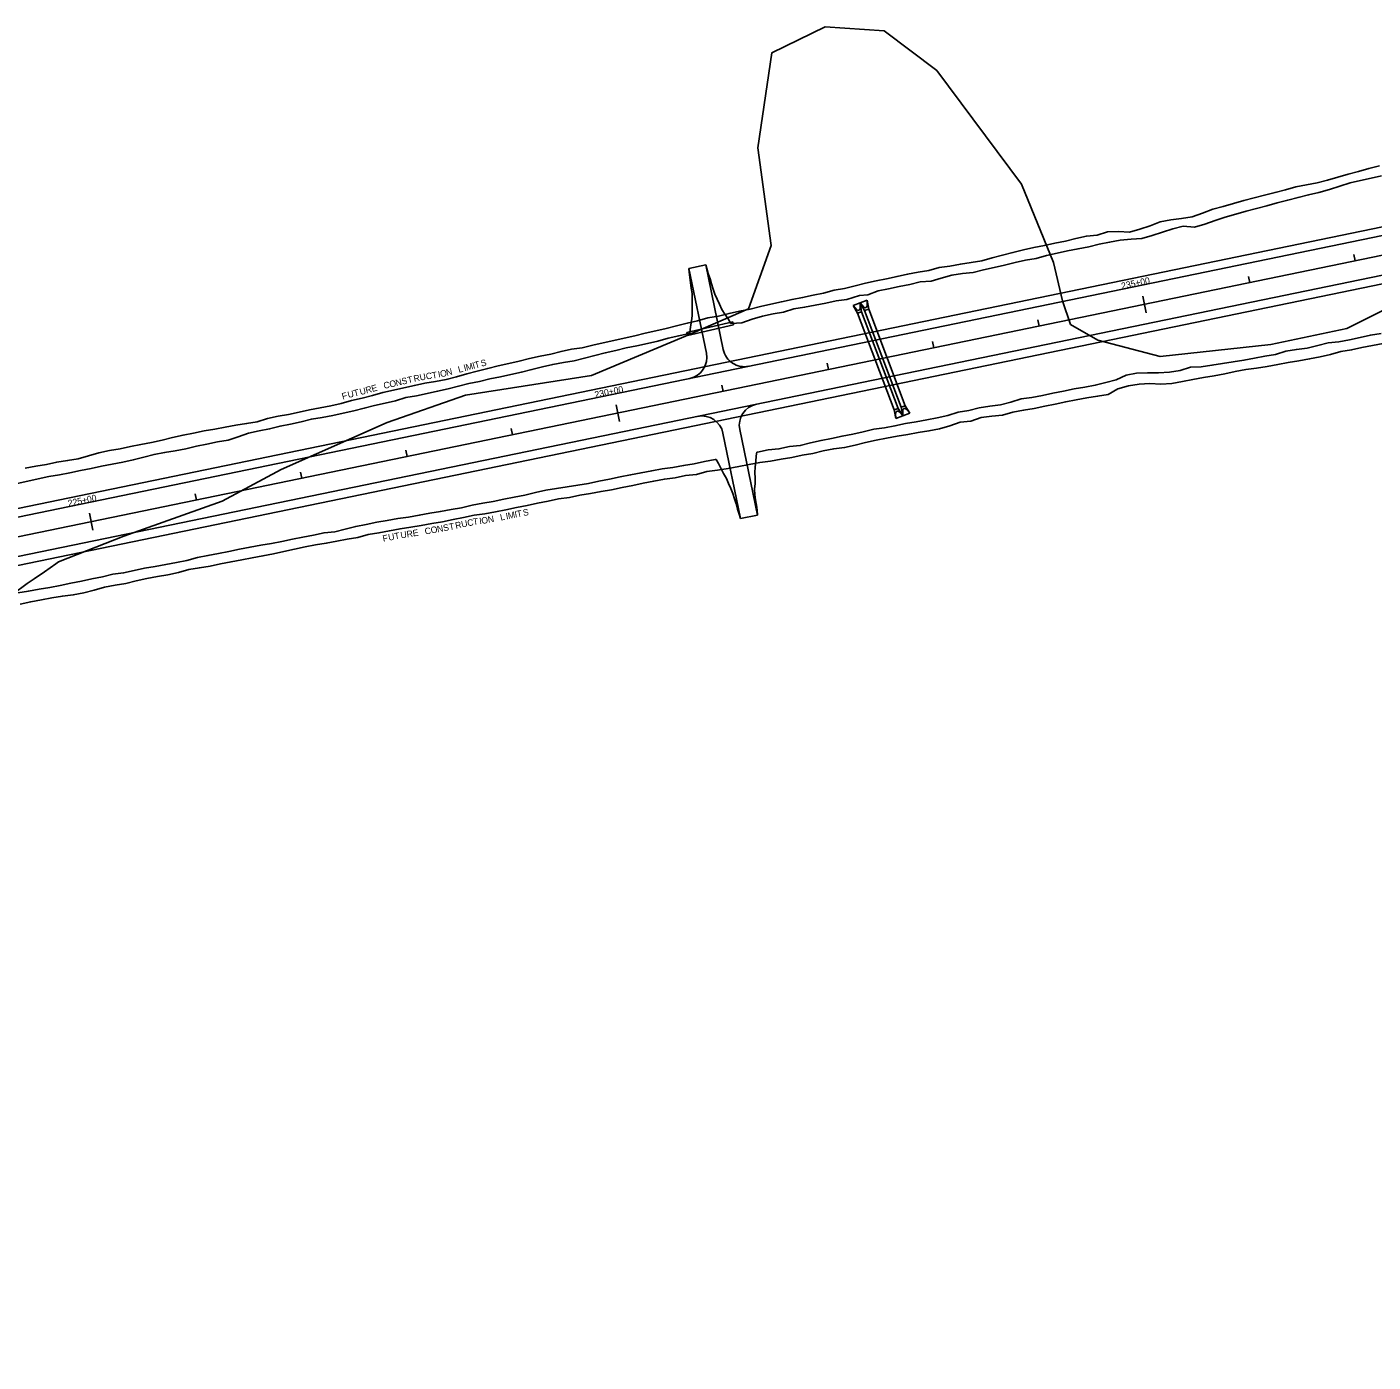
# Model space of a CAD drawing. Extents: x 979959 to 994833, y 1835619 to 1845316.
# Drawn here: x 988176 to 989427, y 1837739 to 1838981 of the extents above; entities that cross this region are included whole.
import ezdxf

# ---------------------------------------------------------------- set-up
doc = ezdxf.new("R2010")
doc.units = 0
for name, color, linetype in [('43', 7, 'Continuous'), ('Future 5 Lane Construction Limits', 7, 'Continuous'), ('R_Drainage', 7, 'Continuous'), ('R_Horz Alg', 7, 'Continuous'), ('R_Horz Alg Stationing', 7, 'Continuous'), ('R_Proposed Const Limits', 7, 'Continuous'), ('R_Proposed Road', 7, 'Continuous')]:
    doc.layers.add(name, color=color, linetype=linetype)

msp = doc.modelspace()

# ---------------------------------------------------------------- linework, layer by layer
at = {"layer": '43'}
msp.add_lwpolyline([(988162.8, 1838452.8), (988176.1, 1838462.9), (988182.4, 1838467.2), (988192, 1838473.5), (988202.5, 1838481), (988205.2, 1838483), (988266, 1838506.7), (988357.2, 1838539.5), (988412, 1838568.7), (988510.6, 1838612.5), (988583.6, 1838638.1), (988700.5, 1838656.4), (988788.1, 1838692.9), (988846.5, 1838718.4), (988867.6, 1838777.2), (988855.3, 1838867.9), (988868.4, 1838956.4), (988917.8, 1838980.5), (988972.9, 1838976.8), (989021.6, 1838940.1), (989100.5, 1838834.2), (989130.3, 1838761.3), (989138.6, 1838725.7), (989145.9, 1838703.8), (989171.4, 1838689.2), (989229.4, 1838673.9), (989332.3, 1838685.2), (989403, 1838700.1), (989504.6, 1838750.9)], dxfattribs=at)
at = {"layer": 'Future 5 Lane Construction Limits'}
for points in [[(988389.8, 1838613.2), (988399.4, 1838616.2), (988409.2, 1838618.4), (988419, 1838620.1), (988428.8, 1838622.1), (988438.6, 1838624.3), (988448.4, 1838626.3), (988458.2, 1838628), (988468, 1838630.3), (988477.6, 1838633), (988487.4, 1838635.3), (988497, 1838637.8), (988506.7, 1838640.5), (988516.5, 1838642.6), (988526.2, 1838644.9), (988536, 1838647.1), (988545.7, 1838649.2), (988555.6, 1838650.7), (988565.5, 1838652.6), (988575.2, 1838655), (988584.8, 1838657.7), (988594.5, 1838660.3), (988604.2, 1838662.9), (988613.9, 1838665.2), (988623.7, 1838667.3), (988633.4, 1838669.6), (988643.1, 1838672.1), (988652.9, 1838674.1), (988662.8, 1838676), (988672.4, 1838678.6), (988682.2, 1838680.8), (988692.1, 1838682.1), (988701.9, 1838684.4), (988711.6, 1838686.6), (988721.4, 1838688.8), (988731.1, 1838691.1), (988740.9, 1838693.2), (988750.6, 1838695.5), (988760.4, 1838697.7), (988770.1, 1838700), (988779.8, 1838702.5), (988789.6, 1838704.8), (988799.3, 1838707.1), (988808.9, 1838709.8), (988818.8, 1838711.6), (988828.5, 1838714), (988838.3, 1838716), (988848.1, 1838718.1), (988857.8, 1838720.4), (988867.5, 1838722.7), (988877.3, 1838724.9), (988887.1, 1838727), (988896.9, 1838728.8), (988906.7, 1838730.9), (988916.5, 1838732.9), (988926.2, 1838735.5), (988936, 1838737.3), (988945.7, 1838739.6), (988955.4, 1838742.2), (988965.2, 1838744.2), (988975, 1838746.2), (988984.7, 1838748.5), (988994.6, 1838750.4), (989004.4, 1838752.3), (989014.2, 1838754), (989023.9, 1838756.6), (989033.8, 1838758.1), (989043.7, 1838759.9), (989053.6, 1838761.4), (989063.5, 1838762.8), (989073.1, 1838765.7), (989082.8, 1838768.3), (989092.5, 1838770.6), (989102.2, 1838773), (989112, 1838775.2), (989121.7, 1838777.3), (989131.5, 1838779.3), (989141.3, 1838781.3), (989151.1, 1838783.7), (989160.8, 1838785.9), (989170.8, 1838786.8), (989180.4, 1838789.9), (989190.5, 1838790.3), (989200.9, 1838789.7), (989210.5, 1838792.4), (989220.1, 1838795.6), (989229.5, 1838799.3), (989239.3, 1838801.2), (989249.3, 1838802.4), (989259.2, 1838803.9), (989268.7, 1838807.4), (989278.2, 1838810.9), (989287.9, 1838813.5), (989297.5, 1838816.2), (989307.2, 1838818.9), (989316.8, 1838821.5), (989326.5, 1838824.1), (989336.2, 1838826.6), (989345.9, 1838829), (989355.6, 1838831.6), (989365.4, 1838833.6), (989375.2, 1838835.6), (989384.9, 1838838), (989394.5, 1838840.8), (989404.2, 1838843.5), (989413.9, 1838846), (989423.5, 1838848.7), (989433.2, 1838851.4)], [(988169.5, 1838443.6), (988179.3, 1838445.8), (988189.2, 1838447.5), (988199, 1838449.3), (988208.8, 1838451.1), (988218.8, 1838452.2), (988228.6, 1838454.2), (988238.3, 1838456.7), (988248, 1838459.3), (988257.8, 1838461.2), (988267.7, 1838462.8), (988277.4, 1838465.2), (988287.2, 1838467.3), (988297, 1838469.2), (988306.9, 1838470.9), (988316.6, 1838473), (988326.3, 1838475.8), (988336.1, 1838477.5), (988346, 1838479), (988355.8, 1838481.1), (988365.6, 1838483), (988375.5, 1838484.8), (988385.3, 1838486.8), (988395.1, 1838488.4), (988404.9, 1838490.5), (988414.7, 1838492.6), (988424.5, 1838494.7), (988434.3, 1838496.8), (988444.1, 1838498.7), (988454, 1838500.2), (988463.8, 1838502.1), (988473.6, 1838503.9), (988483.5, 1838505.7), (988493.1, 1838508.4), (988503, 1838509.9), (988512.8, 1838511.9), (988522.7, 1838513.7), (988532.6, 1838515.2), (988542.4, 1838516.8), (988552.3, 1838518.5), (988562.2, 1838520.2), (988572, 1838522.2), (988581.7, 1838524.3), (988591.5, 1838526.3), (988601.5, 1838527.6), (988611.3, 1838529.4), (988621.1, 1838531.4), (988630.9, 1838533.4), (988640.7, 1838535.4), (988650.5, 1838537.5), (988660.3, 1838539.5), (988670.1, 1838541.5), (988680.1, 1838542.7), (988689.8, 1838544.8), (988699.7, 1838546.6), (988709.5, 1838548.4), (988719.4, 1838550), (988729.2, 1838552.1), (988739, 1838553.9), (988748.7, 1838556.2), (988758.6, 1838558.1), (988768.4, 1838559.9), (988778.4, 1838561.2), (988788.2, 1838563.1), (988798.2, 1838564.1), (988807.8, 1838566.9), (988817.8, 1838568.1), (988827.7, 1838569.7), (988837.5, 1838571.6), (988847.3, 1838573.4), (988857.1, 1838575.2), (988867, 1838576.7), (988876.9, 1838578.4), (988886.8, 1838580), (988896.6, 1838582.1), (988906.4, 1838583.8), (988916.1, 1838586.1), (988925.9, 1838588.2), (988935.9, 1838589.2), (988945.7, 1838591.5), (988955.4, 1838594), (988965.2, 1838596), (988975, 1838598), (988984.8, 1838599.8), (988994.7, 1838601.4), (989004.5, 1838603.1), (989014.4, 1838604.7), (989024.3, 1838606.6), (989033.9, 1838609.5), (989043.4, 1838612.7), (989053.4, 1838613.7), (989062.9, 1838617.1), (989072.9, 1838618.3), (989082.9, 1838619.3), (989092.5, 1838622.3), (989102.4, 1838623.9), (989112.2, 1838625.6), (989122, 1838627.6), (989131.8, 1838629.7), (989141.6, 1838631.9), (989151.4, 1838633.7), (989161.2, 1838635.5), (989171.1, 1838637), (989181, 1838638.7), (989190.1, 1838643.9), (989199.8, 1838646.7), (989209.7, 1838648.1), (989219.8, 1838648.8), (989230.1, 1838648.1), (989240.2, 1838648.8), (989250, 1838650.7), (989259.8, 1838652.6), (989269.7, 1838654.3), (989279.5, 1838655.9), (989289.4, 1838657.8), (989299.1, 1838660), (989309, 1838661.8), (989318.9, 1838663.2), (989328.8, 1838664.6), (989338.7, 1838666.4), (989348.5, 1838668.3), (989358.3, 1838670), (989368.2, 1838671.7), (989378, 1838673.7), (989387.8, 1838675.7), (989397.4, 1838678.5), (989407.3, 1838680), (989417, 1838682.4), (989426.9, 1838684.2), (989436.7, 1838686)], [(988174.1, 1838570.2), (988183.9, 1838571.9), (988193.8, 1838573.4), (988203.5, 1838575.8), (988213.5, 1838577.1), (988223.3, 1838578.8), (988233, 1838581.4), (988242.6, 1838584.2), (988252.4, 1838586.4), (988262.3, 1838587.9), (988272.1, 1838590.1), (988281.8, 1838592.1), (988291.7, 1838594), (988301.4, 1838596.2), (988311.1, 1838598.6), (988320.9, 1838600.8), (988330.7, 1838602.7), (988340.5, 1838604.7), (988350.4, 1838606.3), (988360.2, 1838608.3), (988370, 1838610), (988380, 1838611.5), (988389.8, 1838613.2)]]:
    msp.add_lwpolyline(points, dxfattribs=at)
at = {"layer": 'R_Drainage'}
for p, q in [((988943.8, 1838721.3), (988950.4, 1838723.7)), ((988948.1, 1838714.1), (988943.8, 1838721.3)), ((988947.2, 1838717.4), (988943.8, 1838721.3)), ((988950.4, 1838723.7), (988956.9, 1838726.2)), ((988951.8, 1838715.6), (988950.4, 1838723.7)), ((988950.4, 1838718.6), (988950.4, 1838723.7)), ((988954.6, 1838716.6), (988950.4, 1838723.7)), ((988953.7, 1838719.9), (988950.4, 1838723.7)), ((988954.6, 1838716.6), (988958.4, 1838718)), ((988958.4, 1838718), (988956.9, 1838726.2)), ((988956.9, 1838721.1), (988956.9, 1838726.2)), ((988958.4, 1838718), (988992.3, 1838628.2)), ((988789.2, 1838696.4), (988832.1, 1838706.2)), ((988832.8, 1838703.3), (988832.1, 1838706.2)), ((988948.1, 1838714.1), (988951.8, 1838715.6)), ((988948.1, 1838714.1), (988982, 1838624.3)), ((988951.8, 1838715.6), (988985.7, 1838625.7)), ((988954.6, 1838716.6), (988988.5, 1838626.8)), ((988789.9, 1838693.5), (988789.2, 1838696.4)), ((988789.9, 1838693.5), (988832.8, 1838703.3)), ((988982, 1838624.3), (988985.7, 1838625.7)), ((988982, 1838624.3), (988983.5, 1838616.2)), ((988983.4, 1838621.3), (988983.5, 1838616.2)), ((988983.5, 1838616.2), (988990, 1838618.6)), ((988985.7, 1838625.7), (988990, 1838618.6)), ((988986.6, 1838622.5), (988990, 1838618.6)), ((988988.5, 1838626.8), (988992.3, 1838628.2)), ((988988.5, 1838626.8), (988990, 1838618.6)), ((988990, 1838623.7), (988990, 1838618.6)), ((988990, 1838618.6), (988996.6, 1838621.1)), ((988992.3, 1838628.2), (988996.6, 1838621.1)), ((988993.2, 1838625), (988996.6, 1838621.1))]:
    msp.add_line(p, q, dxfattribs=at)
for centre, start, end in [((988948.6, 1838718.6), 220.983, 0.3459), ((988955.1, 1838721.1), 220.983, 0.3459), ((988985.3, 1838621.3), 40.9829, 180.3457), ((988991.8, 1838623.8), 40.9829, 180.3457)]:
    msp.add_arc(centre, 1.83, start, end, dxfattribs=at)
at = {"layer": 'R_Horz Alg'}
msp.add_line((984572.5, 1837764), (990033.8, 1838891.5), dxfattribs=at)
at = {"layer": 'R_Horz Alg Stationing'}
for points in [[(989409.4, 1838768.7), (989410.6, 1838762.8)], [(989311.5, 1838748.5), (989312.7, 1838742.6)], [(989213.1, 1838730.2), (989216.4, 1838714.6)], [(989115.6, 1838708.1), (989116.8, 1838702.2)], [(989017.7, 1838687.8), (989018.9, 1838682)], [(988919.7, 1838667.6), (988921, 1838661.7)], [(988821.8, 1838647.4), (988823, 1838641.5)], [(988723.5, 1838629.1), (988726.7, 1838613.5)], [(988625.9, 1838607), (988627.2, 1838601.1)], [(988528, 1838586.7), (988529.2, 1838580.9)], [(988430.1, 1838566.5), (988431.3, 1838560.7)], [(988332.1, 1838546.3), (988333.4, 1838540.4)], [(988233.8, 1838528.1), (988237, 1838512.4)]]:
    msp.add_lwpolyline(points, dxfattribs=at)
at = {"layer": 'R_Proposed Const Limits'}
for points in [[(988830.2, 1838704.5), (988830.4, 1838704.5), (988840.5, 1838705.4), (988850, 1838708.8), (988859.7, 1838711.3), (988869.4, 1838713.6), (988879.3, 1838715.3), (988888.9, 1838718.2), (988898.8, 1838719.8), (988908.6, 1838721.6), (988918.4, 1838723.4), (988928.2, 1838725.6), (988938.1, 1838727.1), (988949.9, 1838730.6), (988957.7, 1838731.3), (988967.1, 1838735), (988976.9, 1838736.9), (988986.7, 1838739), (988996.5, 1838740.8), (989006.2, 1838743.3), (989016.3, 1838743.9), (989025.9, 1838746.8), (989035.6, 1838749.6), (989045.5, 1838751), (989055.5, 1838752.1), (989065.2, 1838754.4), (989075, 1838756.6), (989084.7, 1838758.9), (989094.4, 1838761.3), (989104.2, 1838763.4), (989114.1, 1838765.1), (989123.7, 1838767.9), (989133.5, 1838769.9), (989143.2, 1838772.2), (989153, 1838774.1), (989162.9, 1838775.8), (989172.6, 1838778.4), (989182.4, 1838780.2), (989192.2, 1838782.1), (989202.3, 1838783), (989212.3, 1838783.7), (989222, 1838786.5), (989231.5, 1838789.6), (989241.1, 1838792.8), (989250.8, 1838795.2), (989261.2, 1838794.2), (989270.8, 1838797), (989280.4, 1838800.3), (989289.9, 1838803.4), (989299.6, 1838806.2), (989309.2, 1838809), (989318.9, 1838811.6), (989328.6, 1838814.2), (989338.2, 1838816.8), (989347.9, 1838819.5), (989357.6, 1838821.9), (989367.3, 1838824.2), (989377, 1838826.6), (989386.7, 1838829.3), (989396.3, 1838832.5), (989405.9, 1838835.4), (989415.6, 1838837.6), (989425.4, 1838839.8), (989435.1, 1838842)], [(988791.9, 1838695.5), (988792, 1838696.4), (988792.8, 1838701.6), (988793.5, 1838706.9), (988794.2, 1838712.1), (988794.2, 1838717.3), (988794.3, 1838722.4), (988794.4, 1838727.5), (988794.1, 1838732.6), (988793.4, 1838737.5), (988792.7, 1838742.5), (988792.1, 1838747.5), (988791.6, 1838752.5), (988791.3, 1838755.8)], [(988830.2, 1838704.5), (988827.7, 1838708.9), (988824.7, 1838713.3), (988821.8, 1838717.8), (988819.7, 1838722.5), (988817.4, 1838727.2), (988815.3, 1838731.8), (988813.7, 1838736.6), (988812.3, 1838741.4), (988810.9, 1838746.2), (988809.2, 1838751), (988807.8, 1838755.8), (988806.9, 1838759.2)], [(988166.8, 1838555.8), (988176.6, 1838558), (988186.3, 1838560.1), (988196.1, 1838562.2), (988206, 1838563.9), (988215.8, 1838565.8), (988225.6, 1838567.9), (988235.4, 1838569.8), (988245.2, 1838572), (988255, 1838573.9), (988264.8, 1838575.8), (988274.6, 1838577.8), (988284.3, 1838580.2), (988294, 1838582.9), (988303.8, 1838584.5), (988313.7, 1838586.3), (988323.5, 1838588.1), (988333.3, 1838590.4), (988343, 1838592.4), (988352.8, 1838594.5), (988362.7, 1838596.1), (988372.3, 1838599.1), (988381.8, 1838602.7), (988391.6, 1838604.7), (988401.4, 1838606.6), (988411.1, 1838609.2), (988420.9, 1838611), (988430.7, 1838613.1), (988440.3, 1838615.7), (988450.2, 1838617.3), (988460.1, 1838619.1), (988469.8, 1838621.3), (988479.6, 1838623.5), (988489.3, 1838625.8), (988499, 1838628.4), (988508.8, 1838630.5), (988518.5, 1838632.7), (988528.1, 1838635.7), (988538, 1838637.5), (988547.8, 1838639.5), (988557.5, 1838641.6), (988567.3, 1838643.9), (988577, 1838646.4), (988586.7, 1838648.7), (988596.5, 1838650.8), (988606.2, 1838653.2), (988616, 1838655), (988625.8, 1838657.2), (988635.5, 1838659.5), (988645.3, 1838661.7), (988655, 1838664.2), (988664.7, 1838666.6), (988674.6, 1838668.2), (988684.4, 1838670), (988694.1, 1838672.5), (988703.8, 1838675), (988713.5, 1838677.2), (988723.3, 1838679.6), (988733, 1838682), (988742.8, 1838684), (988752.6, 1838686.1), (988762.3, 1838688.3), (988772, 1838690.9), (988781.7, 1838693.2), (988791.5, 1838695.4), (988791.9, 1838695.5)], [(988854.3, 1838584.8), (988855.1, 1838585), (988864.9, 1838587), (988874.9, 1838588), (988884.7, 1838590.1), (988894.7, 1838591.1), (988904.4, 1838593.6), (988914.1, 1838595.9), (988923.9, 1838597.8), (988933.7, 1838599.9), (988943.6, 1838601.8), (988953.3, 1838604), (988963.1, 1838606.2), (988973, 1838607.6), (988982.8, 1838609.4), (988992.6, 1838611.5), (989002.5, 1838613.2), (989012.3, 1838615), (989022.1, 1838616.9), (989031.9, 1838619.2), (989041.5, 1838622.1), (989051.4, 1838623.6), (989061.1, 1838626.1), (989070.9, 1838627.7), (989080.9, 1838629.1), (989090.6, 1838631.6), (989100.2, 1838634.5), (989110.1, 1838635.8), (989119.9, 1838637.6), (989129.7, 1838639.9), (989139.5, 1838641.7), (989149.3, 1838643.8), (989159.2, 1838645.5), (989169, 1838647.2), (989178.7, 1838649.6), (989188.4, 1838652.3), (989197.7, 1838656.7), (989207.5, 1838658.5), (989217.7, 1838658.8), (989227.9, 1838658.7), (989238, 1838659.5), (989247.9, 1838661), (989257.5, 1838664), (989267.6, 1838664.4), (989277.5, 1838665.8), (989287.4, 1838667.5), (989297.2, 1838669.1), (989307.2, 1838670.5), (989317, 1838672.3), (989326.8, 1838674.3), (989336.7, 1838675.9), (989346.3, 1838678.9), (989356.1, 1838680.6), (989366.1, 1838681.7), (989375.8, 1838684.1), (989385.5, 1838686.5), (989395.5, 1838687.6), (989405.4, 1838689.5), (989415.2, 1838691.5), (989424.9, 1838693.9), (989434.8, 1838695.4)], [(988854.3, 1838584.8), (988853.9, 1838581.5), (988853.4, 1838576.3), (988852.9, 1838571.1), (988852.6, 1838565.9), (988852.8, 1838560.9), (988852.8, 1838555.8), (988852.3, 1838550.6), (988852.5, 1838545.5), (988853, 1838540.5), (988854, 1838535.6), (988854.6, 1838531), (988855, 1838526.2)], [(988167.4, 1838454), (988177.2, 1838455.8), (988187.1, 1838457.5), (988197, 1838459.2), (988206.8, 1838461), (988216.6, 1838463), (988226.4, 1838465), (988236.2, 1838467), (988246, 1838468.9), (988255.7, 1838471.5), (988265.6, 1838472.7), (988275.4, 1838474.8), (988285.2, 1838477), (988295, 1838478.7), (988304.9, 1838480.4), (988314.7, 1838482.3), (988324.5, 1838484.2), (988334.2, 1838487), (988344, 1838488.8), (988353.8, 1838490.7), (988363.6, 1838492.7), (988373.4, 1838494.8), (988383.3, 1838496.6), (988393.1, 1838498.3), (988403, 1838500), (988412.8, 1838501.9), (988422.6, 1838503.9), (988432.4, 1838505.9), (988442.2, 1838507.8), (988452, 1838510), (988462, 1838510.7), (988471.7, 1838513.4), (988481.4, 1838515.9), (988491.2, 1838517.8), (988501, 1838519.8), (988510.8, 1838521.5), (988520.7, 1838523.2), (988530.6, 1838524.5), (988540.5, 1838526.3), (988550.3, 1838528.1), (988560.2, 1838529.9), (988570.1, 1838531.5), (988579.9, 1838533.2), (988589.6, 1838535.6), (988599.5, 1838537.4), (988609.3, 1838539.1), (988619.1, 1838541.2), (988628.9, 1838543.2), (988638.7, 1838545), (988648.5, 1838547.3), (988658.2, 1838549.7), (988668.1, 1838551.2), (988678, 1838552.8), (988687.9, 1838554.3), (988697.8, 1838555.9), (988707.5, 1838558), (988717.3, 1838559.9), (988727.2, 1838561.9), (988737, 1838563.8), (988746.8, 1838565.8), (988756.6, 1838567.7), (988766.5, 1838569.3), (988776.4, 1838570.8), (988786.2, 1838572.4), (988796.1, 1838574.1), (988805.8, 1838576.4), (988815.7, 1838578), (988816.5, 1838578.2)], [(988816.5, 1838578.2), (988818.8, 1838574.3), (988821.1, 1838569.6), (988823.5, 1838565), (988826.2, 1838560.5), (988828.1, 1838555.8), (988830.3, 1838551.1), (988832, 1838546.4), (988833.7, 1838541.6), (988835, 1838536.8), (988836.5, 1838532), (988838, 1838527.2), (988839.3, 1838523.2)]]:
    msp.add_lwpolyline(points, dxfattribs=at)
at = {"layer": 'R_Proposed Road'}
for p, q in [((984567.2, 1837789.5), (990028.6, 1838916.9)), ((984568.8, 1837781.7), (990030.2, 1838909.1)), ((984576.1, 1837746.4), (990037.5, 1838873.9)), ((984577.7, 1837738.6), (990039.1, 1838866)), ((988791.3, 1838755.8), (988806.9, 1838759.2)), ((988791.3, 1838755.8), (988807.5, 1838677.1)), ((988806.9, 1838759.2), (988823.2, 1838680.4)), ((988838.5, 1838605.9), (988855, 1838526.2)), ((988822.9, 1838602.7), (988839.3, 1838523.2)), ((988855, 1838526.2), (988839.3, 1838523.2))]:
    msp.add_line(p, q, dxfattribs=at)
for centre, start, end in [((988842.8, 1838684.4), 191.6644, 281.6644), ((988787.9, 1838673.1), 281.6644, 11.6644), ((988803.3, 1838598.6), 11.6644, 101.6644), ((988858.1, 1838610), 101.6644, 191.6644)]:
    msp.add_arc(centre, 20, start, end, dxfattribs=at)

# ---------------------------------------------------------------- texts
at = {"layer": 'Future 5 Lane Construction Limits'}
for s, rotation, p in [('M', 15.0058, (988584.6, 1838660.7)), ('I', 15.0058, (988590.8, 1838662.4)), ('T', 15.0323, (988592.7, 1838662.9)), ('S', 15.0323, (988598.4, 1838664.4)), ('T', 12.4265, (988530.2, 1838648.9)), ('R', 12.4516, (988535.9, 1838650.2)), ('U', 12.4516, (988541.5, 1838651.4)), ('C', 8.4541, (988547.1, 1838652.5)), ('T', 10.7334, (988552.8, 1838653.2)), ('I', 10.7334, (988558.5, 1838654.3)), ('O', 10.7334, (988560.5, 1838654.7)), ('N', 13.8241, (988566.2, 1838655.9)), ('L', 15.7673, (988577.5, 1838658.7)), ('I', 15.0058, (988582.7, 1838660.2)), ('T', 13.4836, (988480.2, 1838636.7)), ('U', 14.6327, (988485.9, 1838638)), ('R', 14.6327, (988491.4, 1838639.5)), ('E', 15.4426, (988496.9, 1838640.9)), ('C', 12.1694, (988507.9, 1838643.8)), ('O', 13.4577, (988513.5, 1838645)), ('N', 13.4577, (988519.2, 1838646.3)), ('S', 12.4265, (988524.7, 1838647.7)), ('F', 15.6542, (988469.4, 1838633.8)), ('U', 13.4836, (988474.6, 1838635.3)), ('I', 11.5836, (988629.8, 1838524)), ('T', 11.1975, (988631.7, 1838524.4)), ('S', 11.1975, (988637.5, 1838525.5)), ('S', 11.5053, (988563.3, 1838511.3)), ('T', 11.5053, (988568.8, 1838512.4)), ('R', 12.0989, (988574.6, 1838513.6)), ('U', 12.0989, (988580.2, 1838514.8)), ('C', 11.5568, (988585.8, 1838515.9)), ('T', 7.3231, (988590.8, 1838517.2)), ('I', 7.3231, (988596.7, 1838517.9)), ('O', 7.3231, (988598.6, 1838518.2)), ('N', 10.6385, (988604.8, 1838519.1)), ('L', 11.3924, (988616.3, 1838521.3)), ('I', 11.5836, (988621.6, 1838522.3)), ('M', 11.5836, (988623.5, 1838522.7)), ('F', 11.4639, (988507.1, 1838501.5)), ('U', 10.164, (988512.2, 1838502.6)), ('T', 10.164, (988517.9, 1838503.7)), ('U', 8.9041, (988523.5, 1838504.7)), ('R', 8.9041, (988529.2, 1838505.6)), ('E', 9.3572, (988534.9, 1838506.5)), ('C', 9.6255, (988546.1, 1838508.3)), ('O', 9.8904, (988551.7, 1838509.3)), ('N', 9.8904, (988557.5, 1838510.3))]:
    msp.add_text(s, height=6, rotation=rotation, dxfattribs=at).set_placement(p)
at = {"layer": 'R_Horz Alg Stationing'}
for s, p in [('235+00', (989193.8, 1838736.5)), ('230+00', (988704.2, 1838635.4)), ('225+00', (988214.5, 1838534.3))]:
    msp.add_text(s, height=6, rotation=11.6644, dxfattribs=at).set_placement(p)

doc.saveas('drawing.dxf')
